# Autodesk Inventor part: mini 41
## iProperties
Created: 2026-08
Part Number: mini 41
Document SubType Name: Modeling
Designer: Tomasz Łysek
Density: 1 g/cm^3
Author: Tomasz Łysek
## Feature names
1. Wyciągnięcie proste1 [Extrusion]
2. Wyciągnięcie proste2 [Extrusion]
3. Wyciągnięcie proste3 [Extrusion]
4. Wyciągnięcie proste4 [Extrusion]
5. Wyciągnięcie proste5 [Extrusion]
6. Wyciągnięcie proste6 [Extrusion]
7. Zaokrąglenie1 [Fillet]
8. Zaokrąglenie2 [Fillet]
